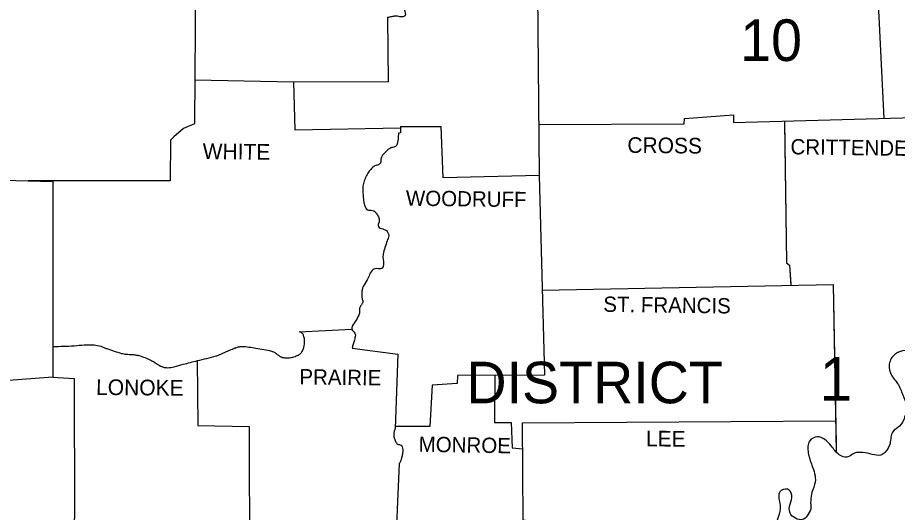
# Model space of a CAD drawing. Extents: x 6028647 to 6035072, y 5366486 to 5368495.
# Drawn here: x 6031371.9 to 6031613, y 5368087.3 to 5368223.1 of the extents above; entities that cross this region are included whole.
import ezdxf

# ---------------------------------------------------------------- set-up
doc = ezdxf.new("R2010")
doc.units = 0
doc.layers.add('Default', color=7, linetype='Continuous')

msp = doc.modelspace()

# ---------------------------------------------------------------- linework, layer by layer
at = {"layer": 'Default'}
msp.add_line((6031476.76, 5368193.17), (6031487.94, 5368193.17), dxfattribs=at)
for points in [[(6031466.94, 5368354.9), (6031466.56, 5368351.87), (6031468.56, 5368351.57), (6031468.46, 5368350.37), (6031470.76, 5368349.87), (6031470.96, 5368348.27), (6031472.06, 5368347.57), (6031472.36, 5368342.77), (6031478.06, 5368342.17), (6031478.06, 5368337.87), (6031480.16, 5368337.57), (6031480.16, 5368335.87), (6031481.96, 5368335.37), (6031481.86, 5368329.57), (6031483.46, 5368329.27), (6031483.86, 5368316.17), (6031475.36, 5368315.37), (6031475.46, 5368312.57), (6031472.86, 5368312.47), (6031473.76, 5368260.87), (6031514.06, 5368259.97), (6031514.76, 5368179.77), (6031488.46, 5368179.07), (6031487.94, 5368193.17)], [(6031374.96, 5368353.47), (6031375.16, 5368329.07), (6031373.46, 5368328.97), (6031373.76, 5368304.07), (6031366.76, 5368303.07), (6031367.36, 5368296.37), (6031369.76, 5368293.27), (6031369.56, 5368285.37), (6031355.97, 5368284.87), (6031355.46, 5368272.67), (6031343.07, 5368272.27), (6031342.47, 5368257.47), (6031343.16, 5368256.27), (6031343.47, 5368232.67), (6031364.86, 5368231.27), (6031364.56, 5368178.57), (6031381.56, 5368178.07), (6031381.56, 5368124.47), (6031368.16, 5368123.47), (6031367.16, 5368111.67), (6031344.67, 5368111.57)], [(6031605.54, 5368280.26), (6031607.26, 5368236.37), (6031609.3, 5368195.4)], [(6031364.86, 5368231.27), (6031416.26, 5368230.97), (6031420.66, 5368233.07), (6031420.36, 5368193.97), (6031417.36, 5368192.67), (6031414.66, 5368190.37), (6031413.76, 5368189.47), (6031413.66, 5368178.27), (6031374.76, 5368178.27)], [(6031473.26, 5368223.07), (6031473.46, 5368205.47), (6031447.46, 5368205.37), (6031420.46, 5368205.88)], [(6031447.46, 5368205.37), (6031447.86, 5368192.27), (6031476.76, 5368192.79)], [(6031514.64, 5368193.76), (6031554.56, 5368193.97), (6031554.66, 5368195.37), (6031568.06, 5368196.37), (6031568.06, 5368194.27), (6031627.63, 5368195.91)], [(6031476.76, 5368193.17), (6031476.76, 5368191.47), (6031476.26, 5368191.37)], [(6031582.06, 5368194.66), (6031582.56, 5368155.77), (6031583.46, 5368155.17), (6031583.78, 5368149.64)], [(6031582.06, 5368194.27), (6031582.56, 5368155.77), (6031583.46, 5368155.17), (6031583.76, 5368149.97)], [(6031582.06, 5368194.27), (6031582.56, 5368155.77), (6031583.46, 5368155.17), (6031583.76, 5368149.97)], [(6031582.06, 5368194.27), (6031582.56, 5368155.77), (6031583.46, 5368155.17), (6031583.76, 5368149.97)], [(6031582.06, 5368194.27), (6031582.56, 5368155.77), (6031583.46, 5368155.17), (6031583.76, 5368149.97)], [(6031514.76, 5368179.77), (6031516.26, 5368124.97), (6031492.46, 5368124.87), (6031492.36, 5368122.67), (6031485.46, 5368122.27), (6031484.86, 5368110.87), (6031475.38, 5368110.87)], [(6031515.63, 5368148.26), (6031595.36, 5368149.87)], [(6031595.36, 5368149.87), (6031596.16, 5368106.07)], [(6031595.36, 5368149.87), (6031596.16, 5368106.07)], [(6031595.36, 5368149.87), (6031596.16, 5368106.07)], [(6031595.36, 5368149.87), (6031596.16, 5368106.07)], [(6031595.36, 5368149.87), (6031596.16, 5368106.07)], [(6031595.36, 5368149.87), (6031596.16, 5368106.07)], [(6031595.36, 5368149.87), (6031596.16, 5368106.07)], [(6031595.36, 5368149.87), (6031596.2, 5368104.07)], [(6031449.06, 5368136.87), (6031463.45, 5368137.57)], [(6031463.56, 5368132.37), (6031476.06, 5368130.77), (6031475.36, 5368110.37)], [(6031421.06, 5368129.07), (6031421.26, 5368111.17), (6031435.36, 5368110.87), (6031435.46, 5368072.47)], [(6031381.56, 5368124.47), (6031387.36, 5368124.07), (6031387.46, 5368085.87), (6031382.26, 5368064.17), (6031393.36, 5368063.67), (6031393.26, 5368044.56)], [(6031502.67, 5368124.91), (6031502.56, 5368111.97), (6031507.16, 5368111.97), (6031507.36, 5368105.07), (6031510.32, 5368104.77)], [(6031514.44, 5368023.17), (6031523.76, 5368023.77), (6031523.66, 5368044.07), (6031516.36, 5368044.57), (6031516.76, 5368084.27), (6031510.46, 5368085.17), (6031510.26, 5368111.87), (6031596.05, 5368112.47)], [(6031476.46, 5368100.77), (6031475.26, 5368073.37), (6031467.06, 5368072.47), (6031467.26, 5368064.37), (6031470.56, 5368064.47), (6031470.66, 5368061.67), (6031475.16, 5368061.17), (6031475.31, 5368056.35)]]:
    msp.add_lwpolyline(points, dxfattribs=at)
for points in [[(6031491.83, 5368260.47), (6031490.94, 5368258.21), (6031489.96, 5368255.97), (6031489.62, 5368255.22), (6031489.27, 5368254.47), (6031488.91, 5368253.72), (6031488.56, 5368252.97), (6031488.32, 5368252.33), (6031488.12, 5368251.67), (6031487.91, 5368251.01), (6031487.66, 5368250.37), (6031487.29, 5368249.91), (6031486.77, 5368249.57), (6031486.22, 5368249.25), (6031485.97, 5368249.07), (6031485.76, 5368248.87), (6031485.59, 5368248.55), (6031485.48, 5368248.17), (6031485.36, 5368247.79), (6031485.16, 5368247.47), (6031484.79, 5368247.26), (6031484.31, 5368247.18), (6031483.84, 5368247.1), (6031483.46, 5368246.87), (6031483.27, 5368246.64), (6031483.09, 5368246.4), (6031482.75, 5368245.91), (6031482.44, 5368245.4), (6031482.16, 5368244.87), (6031481.99, 5368244.43), (6031481.87, 5368243.96), (6031481.75, 5368243.5), (6031481.56, 5368243.07), (6031481.28, 5368242.81), (6031480.88, 5368242.65), (6031480.47, 5368242.51), (6031480.16, 5368242.27), (6031480.03, 5368242.03), (6031479.93, 5368241.76), (6031479.8, 5368241.17), (6031479.67, 5368240.59), (6031479.53, 5368240.19), (6031479.46, 5368240.07), (6031479.18, 5368239.75), (6031478.81, 5368239.48), (6031478.44, 5368239.2), (6031478.16, 5368238.87), (6031478.11, 5368238.4), (6031478.26, 5368237.86), (6031478.38, 5368237.32), (6031478.26, 5368236.87), (6031478.18, 5368236.77), (6031478.1, 5368236.68), (6031477.52, 5368236.17), (6031477.13, 5368235.83), (6031476.76, 5368235.47), (6031476.42, 5368235.1), (6031476.09, 5368234.73), (6031475.79, 5368234.33), (6031475.66, 5368234.11), (6031475.56, 5368233.87), (6031475.44, 5368232.77), (6031475.56, 5368231.67), (6031475.64, 5368230.94), (6031475.72, 5368230.21), (6031475.85, 5368229.49), (6031475.95, 5368229.13), (6031476.06, 5368228.77), (6031476.28, 5368228.32), (6031476.54, 5368227.91), (6031476.82, 5368227.5), (6031477.06, 5368227.07), (6031477.55, 5368225.98), (6031477.77, 5368225.42), (6031477.96, 5368224.87), (6031478.08, 5368224.52), (6031478.14, 5368224.13), (6031478.09, 5368223.77), (6031478, 5368223.61), (6031477.94, 5368223.54), (6031477.86, 5368223.47), (6031477.25, 5368223.24), (6031476.62, 5368223.3), (6031475.99, 5368223.45), (6031475.67, 5368223.49), (6031475.36, 5368223.47), (6031474.84, 5368223.38), (6031474.31, 5368223.29), (6031473.79, 5368223.19), (6031473.26, 5368223.07)], [(6031476.26, 5368191.37), (6031476.2, 5368190.54), (6031476.13, 5368189.71), (6031476, 5368188.89), (6031475.9, 5368188.48), (6031475.83, 5368188.27), (6031475.76, 5368188.07), (6031475.44, 5368187.7), (6031474.93, 5368187.53), (6031474.36, 5368187.4), (6031474.09, 5368187.31), (6031473.86, 5368187.17), (6031472.69, 5368186.14), (6031471.66, 5368184.97), (6031471.48, 5368184.5), (6031471.43, 5368183.96), (6031471.38, 5368183.42), (6031471.16, 5368182.97), (6031470.98, 5368182.82), (6031470.77, 5368182.71), (6031470.28, 5368182.56), (6031469.78, 5368182.42), (6031469.36, 5368182.17), (6031468.89, 5368181.69), (6031468.45, 5368181.19), (6031468.03, 5368180.66), (6031467.66, 5368180.07), (6031466.98, 5368178.65), (6031466.56, 5368177.17), (6031466.48, 5368175.67), (6031466.56, 5368174.17), (6031466.63, 5368173.31), (6031466.75, 5368172.45), (6031466.95, 5368171.61), (6031467.09, 5368171.19), (6031467.26, 5368170.77), (6031467.73, 5368170.37), (6031468.43, 5368170.26), (6031469.16, 5368170.18), (6031469.76, 5368169.87), (6031469.96, 5368169.64), (6031470.15, 5368169.41), (6031470.48, 5368168.92), (6031470.96, 5368167.87), (6031470.99, 5368167.35), (6031470.84, 5368166.81), (6031470.71, 5368166.27), (6031470.76, 5368165.77), (6031471.23, 5368165.33), (6031471.92, 5368165.09), (6031472.64, 5368164.84), (6031473.16, 5368164.37), (6031473.34, 5368164.07), (6031473.49, 5368163.77), (6031473.58, 5368163.47), (6031473.56, 5368163.17), (6031473.16, 5368161.87), (6031472.06, 5368158.17), (6031471.99, 5368157.56), (6031472.04, 5368156.93), (6031472.13, 5368156.3), (6031472.16, 5368155.67), (6031472.12, 5368155.12), (6031472.06, 5368154.84), (6031471.96, 5368154.57), (6031471.44, 5368154.19), (6031470.64, 5368154.18), (6031469.83, 5368154.19), (6031469.26, 5368153.87), (6031467.66, 5368151.17), (6031466.56, 5368149.27), (6031466.43, 5368148.96), (6031466.22, 5368148.03), (6031466.19, 5368147.4), (6031466.16, 5368146.77), (6031466.21, 5368146.32), (6031466.34, 5368145.87), (6031466.45, 5368145.42), (6031466.46, 5368144.97), (6031466.33, 5368144.6), (6031466.09, 5368144.26), (6031465.84, 5368143.93), (6031465.66, 5368143.57), (6031465.59, 5368143.05), (6031465.57, 5368142.51), (6031465.53, 5368141.97), (6031465.36, 5368141.47), (6031464.36, 5368139.67), (6031463.46, 5368137.97), (6031463.5, 5368137.48), (6031463.89, 5368136.98), (6031464.32, 5368136.48), (6031464.46, 5368135.97), (6031464.33, 5368135.28), (6031464.16, 5368134.57), (6031464.01, 5368134.02), (6031463.83, 5368133.47), (6031463.56, 5368132.37)], [(6031632.66, 5368187.37), (6031633.06, 5368184.47), (6031631.36, 5368181.37), (6031630.76, 5368178.27), (6031631.06, 5368175.17), (6031627.86, 5368173.47), (6031625.06, 5368171.47), (6031626.66, 5368169.07), (6031629.66, 5368166.87), (6031632.66, 5368165.17), (6031634.56, 5368163.47), (6031635.06, 5368159.37), (6031635.56, 5368156.77), (6031636.56, 5368153.17), (6031636.96, 5368150.67), (6031635.16, 5368147.67), (6031633.06, 5368147.07), (6031630.86, 5368147.77), (6031628.26, 5368147.97), (6031626.16, 5368145.97), (6031624.66, 5368143.17), (6031623.16, 5368140.37), (6031622.06, 5368137.97), (6031620.96, 5368135.37), (6031618.76, 5368132.37), (6031616.06, 5368131.87), (6031612.86, 5368131.07), (6031610.96, 5368128.87), (6031611.26, 5368125.17), (6031613.06, 5368122.67), (6031614.46, 5368119.57), (6031615.46, 5368116.87), (6031614.96, 5368113.47), (6031613.56, 5368110.97), (6031611.76, 5368109.47), (6031610.96, 5368106.27), (6031609.66, 5368103.87), (6031608.46, 5368103.07), (6031606.06, 5368103.27), (6031603.46, 5368103.77), (6031601.26, 5368103.57), (6031599.16, 5368102.47), (6031597.06, 5368103.17), (6031594.86, 5368105.57), (6031593.06, 5368107.37), (6031591.06, 5368108.07), (6031588.96, 5368106.97), (6031588.56, 5368103.67), (6031589.56, 5368100.27), (6031590.46, 5368095.67), (6031589.56, 5368092.87), (6031589.26, 5368088.27)], [(6031381.56, 5368132.86), (6031387.36, 5368133.07), (6031392.86, 5368133.27), (6031394.63, 5368132.92), (6031395.5, 5368132.58), (6031395.93, 5368132.42), (6031396.36, 5368132.27), (6031400.36, 5368130.97), (6031400.94, 5368130.83), (6031401.52, 5368130.75), (6031402.71, 5368130.67), (6031403.9, 5368130.59), (6031405.06, 5368130.37), (6031408.36, 5368129.07), (6031408.86, 5368128.83), (6031409.34, 5368128.54), (6031410.29, 5368127.91), (6031411.75, 5368127.18), (6031412.01, 5368127.11), (6031412.26, 5368127.07), (6031412.88, 5368127.04), (6031414.76, 5368127.3), (6031416.02, 5368127.63), (6031417.26, 5368127.97), (6031421.16, 5368128.97), (6031426.26, 5368130.27), (6031427.11, 5368130.55), (6031427.93, 5368130.92), (6031428.74, 5368131.31), (6031429.56, 5368131.67), (6031430.03, 5368131.86), (6031431.44, 5368132.44), (6031432.4, 5368132.74), (6031432.88, 5368132.83), (6031433.36, 5368132.87), (6031435.26, 5368132.71), (6031437.16, 5368132.37), (6031439.32, 5368132), (6031441.46, 5368131.57), (6031442.19, 5368131.28), (6031442.85, 5368130.82), (6031443.5, 5368130.34), (6031444.16, 5368129.97), (6031445.34, 5368129.73), (6031446.61, 5368129.8), (6031447.89, 5368130.13), (6031448.5, 5368130.38), (6031449.06, 5368130.67), (6031449.67, 5368131.23), (6031450.12, 5368132.04), (6031450.51, 5368134.07), (6031450.18, 5368135.94), (6031449.73, 5368136.57), (6031449.06, 5368136.87)], [(6031475.36, 5368110.37), (6031475.25, 5368110.13), (6031475.16, 5368109.88), (6031475.03, 5368109.38), (6031474.97, 5368108.87), (6031474.96, 5368108.62), (6031474.96, 5368108.37), (6031475.04, 5368107.83), (6031475.21, 5368107.3), (6031475.46, 5368106.78), (6031475.61, 5368106.52), (6031475.76, 5368106.27), (6031475.9, 5368106.13), (6031476.08, 5368106.04), (6031476.5, 5368105.94), (6031476.9, 5368105.83), (6031477.06, 5368105.73), (6031477.12, 5368105.66), (6031477.16, 5368105.57), (6031477.21, 5368105.45), (6031477.26, 5368105.33), (6031477.41, 5368104.57), (6031477.42, 5368104.07), (6031477.4, 5368103.82), (6031477.36, 5368103.57), (6031477.17, 5368102.57), (6031477.04, 5368102.07), (6031476.96, 5368101.82), (6031476.86, 5368101.57), (6031476.68, 5368101.16), (6031476.46, 5368100.77)], [(6031589.26, 5368088.27), (6031586.96, 5368085.37), (6031583.56, 5368087.17), (6031583.56, 5368089.57), (6031584.06, 5368092.07), (6031582.86, 5368093.67), (6031580.76, 5368092.97), (6031580.76, 5368089.87), (6031580.56, 5368086.87), (6031579.96, 5368082.57), (6031581.36, 5368081.27), (6031584.56, 5368080.87), (6031586.86, 5368080.27), (6031588.26, 5368077.97), (6031588.16, 5368075.17), (6031587.06, 5368072.47), (6031585.46, 5368070.27), (6031582.96, 5368069.47), (6031580.96, 5368070.77), (6031580.16, 5368073.37), (6031579.26, 5368075.67), (6031577.56, 5368077.37), (6031575.76, 5368075.47), (6031575.36, 5368071.97), (6031575.46, 5368068.97), (6031575.46, 5368064.87), (6031578.06, 5368062.17), (6031579.66, 5368059.07), (6031579.16, 5368056.27), (6031577.26, 5368052.97), (6031576.46, 5368050.07), (6031575.66, 5368046.17), (6031575.76, 5368041.87), (6031575.06, 5368037.67), (6031573.66, 5368034.87), (6031571.06, 5368032.57), (6031569.36, 5368031.07), (6031567.96, 5368029.57), (6031567.26, 5368026.57), (6031566.76, 5368024.47), (6031564.86, 5368021.97), (6031563.36, 5368021.77), (6031562.16, 5368022.77), (6031561.76, 5368024.47), (6031561.76, 5368026.17), (6031560.96, 5368027.87), (6031558.46, 5368028.57), (6031556.46, 5368028.47), (6031555.56, 5368027.07), (6031556.86, 5368023.17), (6031557.36, 5368020.67), (6031556.66, 5368017.27), (6031557.06, 5368016.87), (6031553.46, 5368014.97), (6031550.56, 5368014.67), (6031548.16, 5368013.97), (6031545.86, 5368012.47), (6031544.76, 5368010.27), (6031543.16, 5368008.47), (6031541.76, 5368006.77), (6031539.86, 5368005.97), (6031537.76, 5368006.37), (6031534.96, 5368006.67), (6031533.36, 5368004.67), (6031533.86, 5368001.77), (6031535.76, 5368000.07), (6031538.56, 5367999.27), (6031541.46, 5367999.47), (6031544.26, 5367999.77), (6031546.86, 5367998.37), (6031546.36, 5367995.67), (6031543.86, 5367994.37), (6031540.16, 5367993.97), (6031537.16, 5367994.27), (6031533.56, 5367993.47), (6031531.76, 5367991.17), (6031532.76, 5367987.67), (6031536.66, 5367986.27), (6031538.46, 5367982.97), (6031538.56, 5367979.87), (6031537.26, 5367975.77), (6031535.46, 5367973.87), (6031531.96, 5367973.07), (6031529.26, 5367972.57), (6031528.86, 5367967.97), (6031527.66, 5367965.67), (6031525.56, 5367964.97), (6031522.56, 5367966.47), (6031520.76, 5367967.17), (6031518.56, 5367968.17), (6031515.76, 5367969.87), (6031513.66, 5367969.57), (6031514.26, 5367965.17), (6031514.46, 5367964.97), (6031516.86, 5367961.67), (6031519.26, 5367959.07), (6031520.36, 5367955.97)]]:
    msp.add_spline(points, degree=3, dxfattribs=at)

# ---------------------------------------------------------------- texts
for s, height, p in [('10', 11.4, (6031569.89, 5368211.17)), ('DISTRICT', 11.4, (6031494.86, 5368117.27)), ('1', 12, (6031591.66, 5368117.97))]:
    msp.add_text(s, height=height, dxfattribs=at).set_placement(p)
for s, height, rotation, p in [('WHITE', 4.301, 359.3139, (6031422.56, 5368184.27)), ('CROSS', 4.3, 359.3839, (6031538.96, 5368185.97)), ('CRITTENDEN', 4.201, 359.213, (6031583.66, 5368185.57)), ('WOODRUFF', 4.199, 359.2748, (6031478.26, 5368171.47)), ('ST. FRANCIS', 4.1993, 359.2216, (6031532.36, 5368142.37)), ('PRAIRIE', 4.2, 359.2116, (6031449.06, 5368122.47)), ('LONOKE', 4.301, 359.4974, (6031393.36, 5368119.57)), ('LEE', 4.301, 359.4327, (6031544.06, 5368105.47)), ('MONROE', 4.199, 359.0331, (6031481.76, 5368103.97))]:
    msp.add_text(s, height=height, rotation=rotation, dxfattribs=at).set_placement(p)

doc.saveas('drawing.dxf')
